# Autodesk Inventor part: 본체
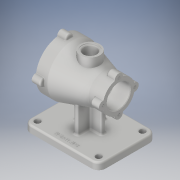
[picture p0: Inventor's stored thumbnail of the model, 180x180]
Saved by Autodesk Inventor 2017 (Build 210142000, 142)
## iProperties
Part Number: 본체
Material: 알루미늄 6061
Document SubType Name: Modeling
Designer: 222
Density: 2.7 g/cm^3
Appearance: 알루미늄 - 평지
Mass: 1049.76 g
Surface Area: 851.002 cm^2
Volume: 388.802 cm^3
Author: 222
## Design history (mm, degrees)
sketch "스케치1"
  geometry: L1 (-50, 0)-(50, 0); L2 (-50, 0)-(-50, 44); L3 (-50, 44)-(-30, 44); L4 (-30, 44)-(25, 27.5); L5 (25, 27.5)-(50, 27.5); L6 (50, 27.5)-(50, 0); 2 further points
  constraints: 12 end point, 2 perpendicular, 1 coincident, 1 horizontal, 1 midpoint, 1 parallel, 1 vertical
  dimensions: "d0" = 100 distance of L1.start L1.end; "d1" = 88 diameter of L3 L1; "d2" = 55 diameter of L5 L1; "d3" = 20 distance of L2.end L3.end; "d4" = 25 distance of L4.end L5.end
revolve "회전1" sketch "스케치1" stored, may be unused: angle "d5" = 90 deg
node "작업 평면1"
sketch "스케치2"
  geometry: L1 (65, 50)-(-65, 50); L2 (-65, 50)-(-65, -50); L3 (-65, -50)-(65, -50); L4 (65, -50)-(65, 50); L5 (65, 50)-(-65, -50); L6 (-65, 50)-(65, -50); 1 further point
  constraints: 12 end point, 2 midpoint, 2 parallel, 1 horizontal, 1 perpendicular
  dimensions: "d7" = 130 distance of L2.end L3.end; "d8" = 100 distance of L1.end L2.end
extrude "돌출1" join sketch "스케치2" distance "d9" = 12; taper "d10" = 0 deg
sketch "스케치3"
  geometry: L1 (-4, -25)-(4, -25); L2 (4, -25)-(4, 25); L3 (4, 25)-(-4, 25); L4 (-4, 25)-(-4, -25); L5 (-4, -25)-(4, 25); L6 (4, -25)-(-4, 25); L7 (-24, 4)-(24, 4); L8 (24, 4)-(24, -4); L9 (24, -4)-(-24, -4); L10 (-24, -4)-(-24, 4); L11 (-24, 4)-(24, -4); L12 (24, 4)-(-24, -4); 1 further point
  constraints: 24 end point, 4 midpoint, 4 parallel, 2 horizontal, 2 perpendicular
  dimensions: "d11" = 8 distance of L2.end L3.end; "d12" = 8 distance of L7.end L8.end; "d13" = 48 distance of L8.end L9.end; "d14" = 50 distance of L3.end L1.start
extrude "돌출2" join sketch "스케치3" stored distance "d15" = 12; taper "d16" = 0 deg
sketch "스케치4"
  geometry: C1 r 17 at (0, 0); 1 further point
  constraints: 1 centre point, 1 coincident
  dimensions: "d17" = 34 diameter of C1
extrude "돌출3" join sketch "스케치4" distance "d18" = 45; taper "d19" = 0 deg
sketch "스케치5"
  geometry: C1 r 14 at (0, 0); 1 further point
  constraints: 1 centre point, 1 coincident
  dimensions: "d20" = 28 diameter of C1
extrude "돌출4" cut sketch "스케치5" distance "d21" = 1; taper "d22" = 0 deg
sketch "스케치6"
  geometry: C1 r 11 at (0, 0); 1 further point
  constraints: 1 centre point, 1 coincident
  dimensions: "d23" = 22 diameter of C1
extrude "돌출5" cut sketch "스케치6" distance "d24" = 44; taper "d25" = 0 deg
sketch "스케치7"
  geometry: C1 r 32 at (0, 0); 1 further point
  constraints: 1 centre point, 1 coincident
  dimensions: "d26" = 64 diameter of C1
extrude "돌출6" cut sketch "스케치7" distance "d27" = 23; taper "d28" = 0 deg
sketch "스케치8"
  geometry: C1 r 26 at (0, 0); 1 further point
  constraints: 1 centre point, 1 coincident
  dimensions: "d29" = 52 diameter of C1
extrude "돌출7" cut sketch "스케치8" distance "d30" = 47; taper "d31" = 0 deg
sketch "스케치9"
  geometry: C1 r 20 at (0, 0); 1 further point
  constraints: 1 centre point, 1 coincident
  dimensions: "d32" = 40 diameter of C1
extrude "돌출8" cut sketch "스케치9" distance "d33" = 30; taper "d34" = 0 deg
sketch "스케치10"
  geometry: L1 (-11, 44)-(11, 44) reference; C1 r 7 at (0, 44); 1 further point
  constraints: 1 centre point, 1 midpoint
  dimensions: "d35" = 14 diameter of C1
extrude "돌출9" join sketch "스케치10" distance "d36" = 15; taper "d37" = 0 deg
sketch "스케치11"
  geometry: C1 r 7 at (0, 27.5); 2 further points
  constraints: 2 vertical alignment, 1 centre point, 1 other
  dimensions: "d41" = 14 diameter of C1
extrude "돌출10" join sketch "스케치11" distance "d42" = 15; taper "d43" = 0 deg
sketch "스케치12"
  geometry: C1 r 32 at (0, -44) reference; A1 r 7 centre (0, 0) between (6.978, -0.557) and (-6.978, -0.557) reference; A2 r 44 centre (0, -44) between (-43.443, -50.978) and (-6.978, -87.443) reference; A3 r 7 centre (0, -88) between (-6.978, -87.443) and (6.978, -87.443) reference; A4 r 44 centre (0, -44) between (6.978, -87.443) and (43.443, -50.978) reference; A5 r 7 centre (44, -44) between (43.443, -50.978) and (43.443, -37.022) reference; A6 r 44 centre (0, -44) between (43.443, -37.022) and (6.978, -0.557) reference; A7 r 7 centre (0, 0) between (6.978, -0.557) and (-6.978, -0.557) reference; A8 r 44 centre (0, -44) between (-6.978, -0.557) and (-43.443, -37.022) reference; A9 r 7 centre (-44, -44) between (-43.443, -37.022) and (-43.443, -50.978) reference; 1 further point
hole "구멍1" sketch "스케치12" at (0, 0), (-44, -44), (0, -88), (44, -44) diameter "d47" = 4.134; stored, may be unused: countersink angle "d51" = 90 deg, drill point angle "d53" = 118 deg; dims "d48" = 9, "d49" = 4, "d50" = 2, "d52" = 11
sketch "스케치13"
  geometry: C1 r 20 at (0, -27.5) reference; A1 r 27.5 centre (0, -27.5) between (-26.609, -34.443) and (-6.943, -54.109) reference; A2 r 7 centre (0, -55) between (-6.943, -54.109) and (6.943, -54.109) reference; A3 r 27.5 centre (0, -27.5) between (6.943, -54.109) and (26.609, -34.443) reference; A4 r 7 centre (27.5, -27.5) between (26.609, -34.443) and (26.609, -20.557) reference; A5 r 27.5 centre (0, -27.5) between (26.609, -20.557) and (6.943, -0.891) reference; A6 r 7 centre (0, 0) between (6.943, -0.891) and (-6.943, -0.891) reference; A7 r 27.5 centre (0, -27.5) between (-6.943, -0.891) and (-26.609, -20.557) reference; A8 r 7 centre (-27.5, -27.5) between (-26.609, -20.557) and (-26.609, -34.443) reference; 1 further point
hole "구멍2" sketch "스케치13" at (0, 0), (-27.5, -27.5), (0, -55), (27.5, -27.5) diameter "d54" = 4.134; stored, may be unused: countersink angle "d58" = 90 deg, drill point angle "d60" = 118 deg; dims "d55" = 9, "d56" = 4, "d57" = 2, "d59" = 11
chamfer "모따기1" distance "d61" = 1; stored, may be unused: second distance "d62" = 2, angle "d63" = 45 deg
fillet "모깎기3" dims "d66" = 3
fillet "모깎기4" dims "d67" = 12
sketch "스케치14"
  geometry: L1 (53, 50)-(-53, 50) reference; L2 (65, -38)-(65, 38) reference; L3 (-53, -50)-(53, -50) reference; L4 (-65, 38)-(-65, -38) reference; C1 r 5 at (-53, 38); C2 r 5 at (-53, -38); C3 r 5 at (53, -38); C4 r 5 at (53, 38); A1 r 12 centre (-53, 38) between (-53, 50) and (-65, 38) reference; A2 r 12 centre (53, 38) between (65, 38) and (53, 50) reference; A3 r 12 centre (53, -38) between (53, -50) and (65, -38) reference; A4 r 12 centre (-53, -38) between (-65, -38) and (-53, -50) reference; 1 further point
  constraints: 4 centre point, 4 coincident
  dimensions: "d68" = 10 diameter of C1; "d69" = 10 diameter of C2; "d70" = 10 diameter of C3; "d71" = 10 diameter of C4
extrude "돌출11" cut sketch "스케치14" stored distance "d72" = 15; taper "d73" = 0 deg
fillet "모깎기5" dims "d74" = 3
fillet "모깎기6" dims "d75" = 3
fillet "모깎기7" dims "d76" = 3
fillet "모깎기8" dims "d77" = 3
fillet "모깎기9" dims "d78" = 3
fillet "모깎기10" dims "d79" = 1
node "작업 평면2"
sketch "스케치15"
  geometry: L1 (-53, -50)-(53, -50) reference; 2 further points
  constraints: 1 vertical alignment, 1 other
  dimensions: "d81" = 10 distance from line of point (0, -40) L1
feature "엠보싱1" sketch "스케치15" dims "d0" = 100, "d11" = 8, "d14" = 50, "d82" = 0.5, "d83" = 0
node "솔리드1"
pattern_circular "원형 패턴1" dims angle "d39" = 360 deg
pattern_circular "원형 패턴2" dims angle "d45" = 360 deg
node "투영된 루프1"
node "투영된 루프2"
node "투영된 루프3"
other parameters: "d6" = -82, "d80" = 4.75
